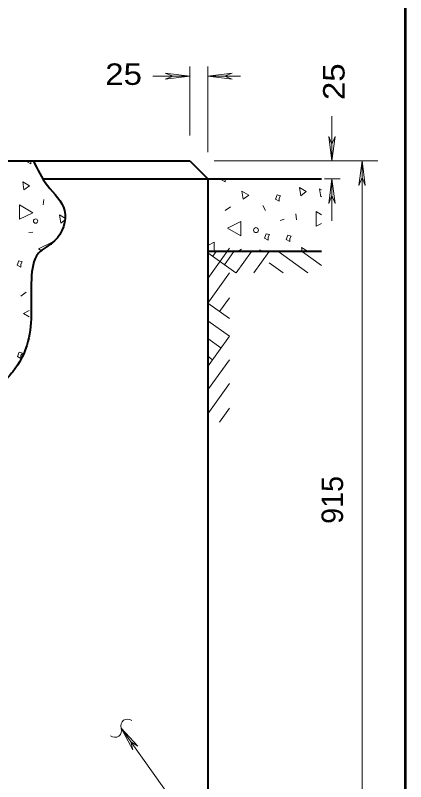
# Model space of a CAD drawing. Extents: x 312583 to 312854, y 144419 to 144597.
# Drawn here: x 312754.44 to 312768.24, y 144523.01 to 144550.14 of the extents above; entities that cross this region are included whole.
import ezdxf

# ---------------------------------------------------------------- set-up
doc = ezdxf.new("R2010")
doc.units = 0
doc.header["$LTSCALE"] = 0.3
doc.layers.add('1', color=7, linetype='Continuous', lineweight=25)
doc.layers.add('2', color=7, linetype='Continuous', lineweight=13)

msp = doc.modelspace()

# ---------------------------------------------------------------- linework, layer by layer
at = {"layer": '1', "lineweight": 53}
msp.add_line((312768.237, 144506.4889), (312768.237, 144585.0846), dxfattribs=at)
at = {"layer": '1', "lineweight": 40}
for p, q in [((312722.2688, 144544.9833), (312760.6021, 144544.9833)), ((312760.6021, 144544.9833), (312761.2385, 144544.3469)), ((312755.4425, 144544.3469), (312765.2635, 144544.3469)), ((312761.2385, 144544.3469), (312761.2385, 144521.9833)), ((312761.2385, 144541.7863), (312765.2635, 144541.7863))]:
    msp.add_line(p, q, dxfattribs=at)
msp.add_spline([(312755.0745, 144544.9833), (312755.5728, 144544.1169), (312756.1785, 144543.2276), (312755.8258, 144542.1543), (312755.2585, 144541.7173), (312755.0055, 144540.7973), (312754.8828, 144538.5893), (312754.3461, 144537.5159), (312754.1851, 144537.3243), (312753.2728, 144536.5346), (312752.7131, 144536.7646), (312751.8468, 144536.6649), (312751.0801, 144536.7263), (312750.2215, 144536.5116), (312749.1635, 144536.4733), (312748.5425, 144536.6803), (312747.8065, 144536.3813), (312747.7145, 144536.2816), (312747.0091, 144536.3889), (312745.9128, 144535.7143), (312745.6291, 144535.6529), (312744.5635, 144536.2126), (312742.9688, 144536.2893), (312742.6315, 144535.8293)], degree=3, dxfattribs=at)
at = {"layer": '2'}
for p, q in [((312760.6021, 144545.8879), (312760.6021, 144548.3336)), ((312761.2385, 144545.2976), (312761.2385, 144548.3336)), ((312759.2988, 144547.9886), (312760.6021, 144547.9886)), ((312759.7358, 144548.0959), (312760.0118, 144547.9886)), ((312760.6021, 144547.9886), (312759.7358, 144548.0959)), ((312759.7358, 144547.8813), (312760.0118, 144547.9886)), ((312760.6021, 144547.9886), (312759.7358, 144547.8813)), ((312761.2385, 144547.9886), (312762.1048, 144548.0959)), ((312761.2385, 144547.9886), (312762.3961, 144547.9886)), ((312761.2385, 144547.9886), (312762.1048, 144547.8813)), ((312762.1048, 144548.0959), (312761.8288, 144547.9886)), ((312762.1048, 144547.8813), (312761.8288, 144547.9886)), ((312765.6331, 144544.9833), (312765.6331, 144546.5703)), ((312765.5257, 144545.8496), (312765.6331, 144545.5736)), ((312765.6331, 144544.9833), (312765.5257, 144545.8496)), ((312765.7404, 144545.8496), (312765.6331, 144545.5736)), ((312765.6331, 144544.9833), (312765.7404, 144545.8496)), ((312761.4685, 144544.9833), (312767.2539, 144544.9833)), ((312766.6945, 144544.9833), (312766.5872, 144544.1169)), ((312766.6945, 144521.9833), (312766.6945, 144544.9833)), ((312766.6945, 144544.9833), (312766.8019, 144544.1169)), ((312766.5872, 144544.1169), (312766.6945, 144544.3929)), ((312766.8019, 144544.1169), (312766.6945, 144544.3929)), ((312761.2385, 144544.1016), (312761.2768, 144544.0939)), ((312765.3674, 144544.3469), (312765.9184, 144544.3469)), ((312765.6331, 144544.3469), (312765.5257, 144543.4806)), ((312765.6331, 144542.8596), (312765.6331, 144544.3469)), ((312765.6331, 144544.3469), (312765.7404, 144543.4806)), ((312755.4271, 144543.4346), (312755.4501, 144543.6186)), ((312765.2328, 144543.7106), (312765.2635, 144543.7413)), ((312765.5257, 144543.4806), (312765.6331, 144543.7566)), ((312765.7404, 144543.4806), (312765.6331, 144543.7566)), ((312762.0435, 144543.3579), (312761.8595, 144543.2276)), ((312763.1935, 144543.4039), (312763.2778, 144543.2353)), ((312764.3588, 144543.1126), (312764.3818, 144542.8979)), ((312765.2635, 144543.0743), (312765.0718, 144543.1893)), ((312756.0405, 144542.7829), (312756.2168, 144542.9133)), ((312763.7991, 144542.8749), (312763.9448, 144542.9209)), ((312754.9135, 144542.4533), (312755.0591, 144542.4609)), ((312762.0051, 144541.9013), (312761.2385, 144540.8279)), ((312762.2275, 144541.0273), (312761.2385, 144541.7326)), ((312761.5375, 144541.7786), (312761.4148, 144541.6099)), ((312762.1661, 144541.7786), (312761.8288, 144541.3109)), ((312762.7871, 144541.7786), (312762.2505, 144541.0196)), ((312762.3195, 144541.7863), (312762.4345, 144541.8553)), ((312763.4158, 144541.7786), (312762.8715, 144541.0196)), ((312764.7805, 144541.0273), (312763.7148, 144541.7863)), ((312765.2635, 144541.2803), (312764.5888, 144541.7709)), ((312763.9065, 144541.0273), (312763.4158, 144541.3723)), ((312762.0051, 144541.0196), (312761.2385, 144539.9463)), ((312754.8215, 144540.3373), (312754.6375, 144540.1993)), ((312762.0051, 144540.1379), (312761.6601, 144539.6549)), ((312761.2385, 144539.9463), (312762.0051, 144539.4096)), ((312761.2385, 144539.3253), (312762.0051, 144538.7809)), ((312762.0051, 144538.7809), (312761.2308, 144537.6923)), ((312761.2385, 144538.6966), (312761.7061, 144538.3669)), ((312761.2385, 144538.0679), (312761.4071, 144537.9453)), ((312762.0051, 144537.9453), (312761.2615, 144536.9103)), ((312762.0051, 144537.1019), (312761.2385, 144536.0363)), ((312762.0051, 144536.2279), (312761.6601, 144535.7373)), ((312758.1795, 144524.9043), (312758.5935, 144524.1299)), ((312758.1795, 144524.9043), (312758.7698, 144524.2603)), ((312758.5935, 144524.1299), (312758.5245, 144524.4213)), ((312758.7698, 144524.2603), (312758.5245, 144524.4213))]:
    msp.add_line(p, q, dxfattribs=at)
for points in [[(312754.8675, 144544.9833), (312754.8598, 144544.9526), (312754.9825, 144544.8836), (312754.9825, 144544.9833)], [(312755.2278, 144544.7073), (312755.2201, 144544.6996), (312755.2431, 144544.6919)], [(312761.7368, 144544.3469), (312761.7215, 144544.3163), (312761.8518, 144544.2473), (312761.8518, 144544.3469)], [(312765.2635, 144543.9559), (312765.1868, 144544.0019), (312765.2328, 144543.7106)], [(312756.2168, 144542.9439), (312756.0021, 144543.0743), (312756.0405, 144542.7829)], [(312765.0718, 144543.1893), (312765.0718, 144542.6756), (312765.2635, 144542.7676)], [(312755.7185, 144542.0163), (312755.7185, 144542.1006), (312755.2508, 144541.8706), (312755.3811, 144541.7939)], [(312761.4685, 144541.7863), (312761.4685, 144542.1083), (312761.2385, 144541.9933)], [(312763.1705, 144541.7863), (312763.0785, 144541.8399), (312763.0861, 144541.7863)], [(312764.7728, 144541.7863), (312764.5581, 144541.9166), (312764.5735, 144541.7863)], [(312754.9288, 144539.6856), (312754.7295, 144539.5859), (312754.9211, 144539.4709)], [(312760.4028, 144520.2046), (312761.5145, 144520.2046), (312758.1795, 144524.9043)]]:
    msp.add_lwpolyline(points, dxfattribs=at)
for points in [[(312754.7371, 144543.9636), (312754.9365, 144544.1093), (312754.6988, 144544.2473)], [(312762.4881, 144543.6263), (312762.6875, 144543.7719), (312762.4498, 144543.9099)], [(312764.5275, 144543.7489), (312764.7191, 144543.9023), (312764.4815, 144544.0403)], [(312763.7608, 144543.6646), (312763.8068, 144543.7489), (312763.6918, 144543.7796), (312763.6305, 144543.6339), (312763.7608, 144543.5573)], [(312754.5838, 144543.4346), (312754.5838, 144542.9209), (312755.0515, 144543.1509)], [(312762.4115, 144542.3306), (312762.4115, 144542.8443), (312761.9438, 144542.6066)], [(312763.3775, 144542.2923), (312763.4235, 144542.3766), (312763.3085, 144542.4073), (312763.2471, 144542.2539), (312763.3775, 144542.1849)], [(312764.1441, 144542.2386), (312764.1901, 144542.3229), (312764.0751, 144542.3536), (312764.0138, 144542.2079), (312764.1441, 144542.1313)], [(312754.6375, 144541.3339), (312754.6835, 144541.4106), (312754.5608, 144541.4489), (312754.5071, 144541.2956), (312754.6375, 144541.2266)], [(312754.6375, 144538.0986), (312754.6911, 144538.1829), (312754.5685, 144538.2136), (312754.5148, 144538.0603), (312754.6375, 144537.9913)]]:
    msp.add_lwpolyline(points, close=True, dxfattribs=at)
for centre, radius in [((312755.1547, 144542.8551), 0.0784), ((312762.9461, 144542.5367), 0.0865)]:
    msp.add_circle(centre, radius, dxfattribs=at)
for centre, start, end in [((312758.4046, 144524.9844), 50.36848, 200.36848), ((312757.9556, 144524.8177), 230.36848, 20.36848)]:
    msp.add_arc(centre, 0.2395, start, end, dxfattribs=at)

# ---------------------------------------------------------------- texts
at = {"layer": '2', "width": 1.15}
msp.add_text('25 ', height=0.76, dxfattribs=at).set_placement((312757.6144, 144547.6772))
msp.add_text('25 ', height=0.76, rotation=90, dxfattribs=at).set_placement((312766.0779, 144547.1386))
at = {"layer": '2'}
msp.add_text('915', height=0.76, rotation=90, dxfattribs=at).set_placement((312766.0232, 144532.1353))

doc.saveas('drawing.dxf')
